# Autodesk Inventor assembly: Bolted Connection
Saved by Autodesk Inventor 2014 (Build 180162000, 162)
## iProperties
Created: 2010-12
Part Number: Bolted Connection
Document SubType Name: Assembly
Designer: Thom Tremblay
ClientObjectVersion: 1
Author: Thom Tremblay
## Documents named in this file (3)
- C:\Inventor 2014 Essentials\Assemblies\Chapter 08\c08-01\Design Accelerator\Bolted Connection3.iam
- C:\Inventor 2014 Essentials\Content Center Files\en-US\ISO 7089\ISO 7089 - 4 - 140 HV.ipt
- C:\Inventor 2014 Essentials\Content Center Files\en-US\ISO 4762\ISO 4762 - M4 x 10ISO.ipt
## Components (16 placed, 2 different names)
1. ISO 4762 M4 x 10:1
2. ISO 7089 4 - 140 HV:1
3. ISO 4762 M4 x 10:2
4. ISO 4762 M4 x 10:3
5. ISO 4762 M4 x 10:4
6. ISO 4762 M4 x 10:5
7. ISO 4762 M4 x 10:6
8. ISO 4762 M4 x 10:7
9. ISO 4762 M4 x 10:8
10. ISO 7089 4 - 140 HV:2
11. ISO 7089 4 - 140 HV:3
12. ISO 7089 4 - 140 HV:4
13. ISO 7089 4 - 140 HV:5
14. ISO 7089 4 - 140 HV:6
15. ISO 7089 4 - 140 HV:7
16. ISO 7089 4 - 140 HV:8
